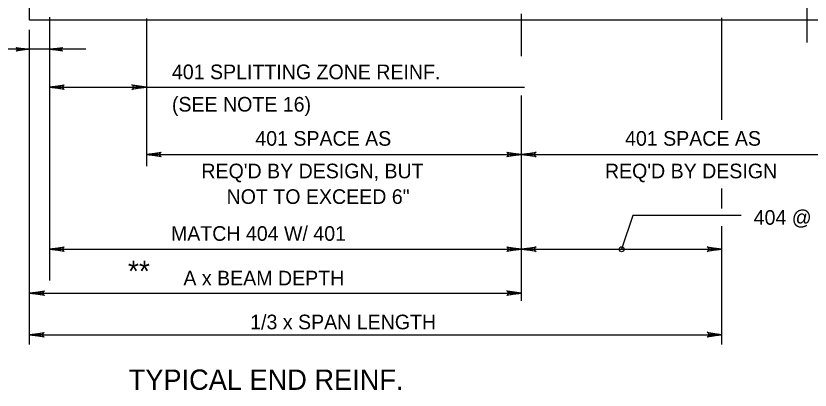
# Model space of a CAD drawing. Extents: x 637933 to 640019, y 298854 to 300042.
# Drawn here: x 638067.4 to 638230.3, y 299634.7 to 299711.4 of the extents above; entities that cross this region are included whole.
import ezdxf

# ---------------------------------------------------------------- set-up
doc = ezdxf.new("R2010")
doc.units = 0
doc.layers.add('1', color=7, linetype='Continuous')

msp = doc.modelspace()

# ---------------------------------------------------------------- linework, layer by layer
at = {"layer": '1'}
for p, q in [((638229.63, 299812.16), (638229.63, 299705.93)), ((638070.19, 299710.48), (638070.19, 299775.48)), ((638074.32, 299711.11), (638074.32, 299657.13)), ((638094.19, 299710.86), (638094.19, 299680.6)), ((638171.07, 299703.13), (638171.07, 299711.8)), ((638212.19, 299690.06), (638212.19, 299710.96)), ((638291.56, 299710.48), (638070.19, 299710.48)), ((638070.19, 299644.05), (638070.19, 299708.55)), ((638069.94, 299704.54), (638059.23, 299704.54)), ((638074.32, 299704.54), (638069.94, 299704.54)), ((638081.73, 299704.54), (638074.32, 299704.54)), ((638074.32, 299696.79), (638171.69, 299696.79)), ((638171.07, 299652.96), (638171.07, 299695.07)), ((638094.19, 299682.98), (638171.07, 299682.98)), ((638171.07, 299682.98), (638244.74, 299682.98)), ((638212.19, 299671.87), (638212.19, 299676.03)), ((638193.94, 299670.48), (638191.63, 299663.55)), ((638216.16, 299670.48), (638193.94, 299670.48)), ((638212.19, 299644.05), (638212.19, 299668.25)), ((638074.32, 299663.55), (638171.07, 299663.55)), ((638171.07, 299663.55), (638212.19, 299663.55)), ((638070.19, 299654.57), (638171.07, 299654.57)), ((638070.19, 299646.04), (638212.19, 299646.04))]:
    msp.add_line(p, q, dxfattribs=at)
for points in [[(638067.57, 299704.79), (638067.69, 299704.66), (638069.94, 299704.54), (638067.57, 299704.79), (638067.44, 299704.91), (638069.94, 299704.54), (638067.69, 299704.41), (638067.57, 299704.29), (638069.94, 299704.54), (638067.44, 299704.16), (638067.57, 299704.29)], [(638076.82, 299704.29), (638076.69, 299704.41), (638074.32, 299704.54), (638076.82, 299704.29), (638076.94, 299704.16), (638074.32, 299704.54), (638076.69, 299704.66), (638076.82, 299704.79), (638074.32, 299704.54), (638076.94, 299704.91), (638076.82, 299704.79)], [(638077.17, 299696.43), (638077.07, 299696.64), (638074.32, 299696.79), (638077.17, 299696.43), (638077.32, 299696.3), (638074.32, 299696.79), (638077.07, 299696.92), (638077.17, 299697.13), (638074.32, 299696.79), (638077.32, 299697.27), (638077.17, 299697.13)], [(638091.34, 299697.15), (638091.45, 299696.94), (638094.19, 299696.79), (638091.34, 299697.15), (638091.19, 299697.27), (638094.19, 299696.79), (638091.45, 299696.65), (638091.35, 299696.45), (638094.19, 299696.79), (638091.19, 299696.31), (638091.35, 299696.45)], [(638097.05, 299682.62), (638096.94, 299682.83), (638094.19, 299682.98), (638097.05, 299682.62), (638097.19, 299682.5), (638094.19, 299682.98), (638096.94, 299683.12), (638097.04, 299683.32), (638094.19, 299682.98), (638097.19, 299683.46), (638097.04, 299683.32)], [(638168.21, 299683.34), (638168.32, 299683.13), (638171.07, 299682.98), (638168.21, 299683.34), (638168.07, 299683.47), (638171.07, 299682.98), (638168.32, 299682.85), (638168.22, 299682.64), (638171.07, 299682.98), (638168.07, 299682.5), (638168.22, 299682.64)], [(638173.92, 299682.62), (638173.81, 299682.83), (638171.07, 299682.98), (638173.92, 299682.62), (638174.07, 299682.5), (638171.07, 299682.98), (638173.81, 299683.12), (638173.91, 299683.32), (638171.07, 299682.98), (638174.07, 299683.46), (638173.91, 299683.32)], [(638077.17, 299663.2), (638077.07, 299663.4), (638074.32, 299663.55), (638077.17, 299663.2), (638077.32, 299663.07), (638074.32, 299663.55), (638077.07, 299663.69), (638077.17, 299663.89), (638074.32, 299663.55), (638077.32, 299664.03), (638077.17, 299663.89)], [(638168.21, 299663.91), (638168.32, 299663.71), (638171.07, 299663.55), (638168.21, 299663.91), (638168.07, 299664.04), (638171.07, 299663.55), (638168.32, 299663.42), (638168.22, 299663.21), (638171.07, 299663.55), (638168.07, 299663.08), (638168.22, 299663.21)], [(638173.92, 299663.2), (638173.81, 299663.4), (638171.07, 299663.55), (638173.92, 299663.2), (638174.07, 299663.07), (638171.07, 299663.55), (638173.81, 299663.69), (638173.91, 299663.89), (638171.07, 299663.55), (638174.07, 299664.03), (638173.91, 299663.89)], [(638209.34, 299663.91), (638209.45, 299663.71), (638212.19, 299663.55), (638209.34, 299663.91), (638209.19, 299664.04), (638212.19, 299663.55), (638209.45, 299663.42), (638209.35, 299663.21), (638212.19, 299663.55), (638209.19, 299663.08), (638209.35, 299663.21)], [(638073.13, 299654.21), (638073.02, 299654.42), (638070.27, 299654.57), (638073.13, 299654.21), (638073.27, 299654.09), (638070.27, 299654.57), (638073.02, 299654.71), (638073.12, 299654.91), (638070.27, 299654.57), (638073.27, 299655.05), (638073.12, 299654.91)], [(638168.21, 299654.93), (638168.32, 299654.72), (638171.07, 299654.57), (638168.21, 299654.93), (638168.07, 299655.05), (638171.07, 299654.57), (638168.32, 299654.44), (638168.22, 299654.23), (638171.07, 299654.57), (638168.07, 299654.09), (638168.22, 299654.23)], [(638073.05, 299645.68), (638072.94, 299645.89), (638070.19, 299646.04), (638073.05, 299645.68), (638073.19, 299645.55), (638070.19, 299646.04), (638072.94, 299646.17), (638073.04, 299646.38), (638070.19, 299646.04), (638073.19, 299646.51), (638073.04, 299646.38)], [(638209.34, 299646.4), (638209.45, 299646.19), (638212.19, 299646.04), (638209.34, 299646.4), (638209.19, 299646.52), (638212.19, 299646.04), (638209.45, 299645.9), (638209.35, 299645.7), (638212.19, 299646.04), (638209.19, 299645.56), (638209.35, 299645.7)]]:
    msp.add_lwpolyline(points, dxfattribs=at)
msp.add_circle((638191.63, 299663.55), 0.51, dxfattribs=at)

# ---------------------------------------------------------------- texts
for s, height, p in [('401 SPLITTING ZONE REINF.', 3, (638099.4, 299698.41)), ('(SEE NOTE 16)', 3, (638099.4, 299691.77)), ('401 SPACE AS', 3, (638116.5, 299684.77)), ('401 SPACE AS', 3, (638192.33, 299684.77)), ("REQ'D BY DESIGN, BUT", 3, (638105.44, 299678.09)), ("REQ'D BY DESIGN", 3, (638188.2, 299678.09)), ('NOT TO EXCEED 6"', 3, (638110.61, 299672.84)), ('404 @ 21" MAX.', 3, (638218.71, 299668.57)), ('MATCH 404 W/ 401', 3, (638099.2, 299665.28)), ('**', 4.32, (638090.38, 299656.9)), ('A x BEAM DEPTH', 3, (638101.75, 299656.14)), ('1/3 x SPAN LENGTH', 3, (638115.45, 299647.14)), ('TYPICAL END REINF.', 4.1665, (638090.54, 299634.73))]:
    msp.add_text(s, height=height, dxfattribs=at).set_placement(p)

doc.saveas('drawing.dxf')
